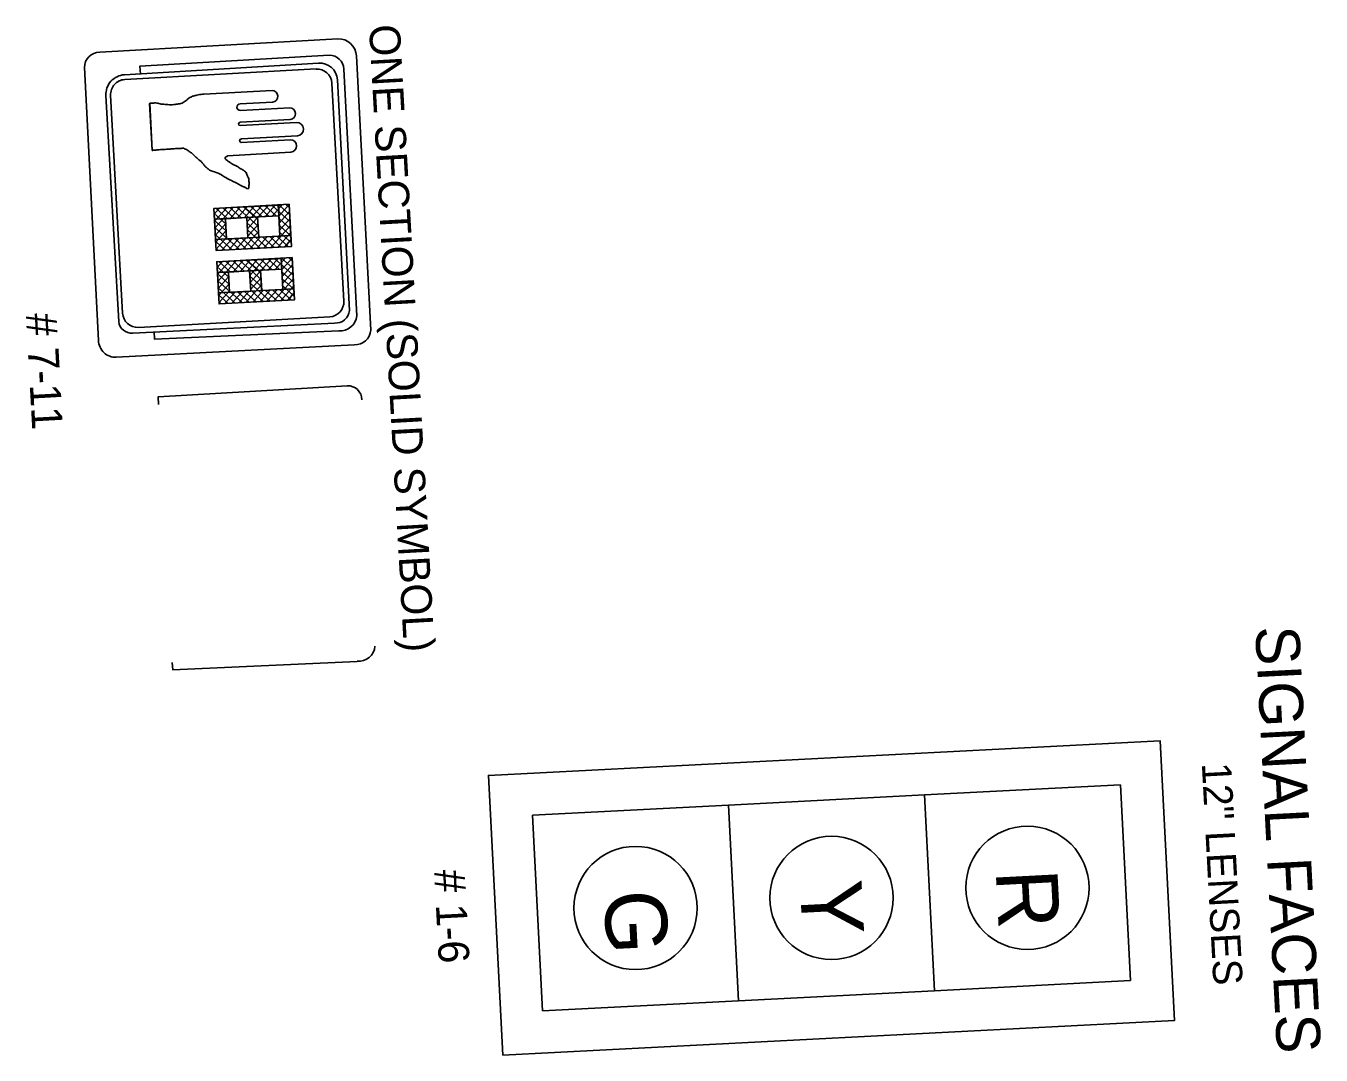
# Model space of a CAD drawing. Extents: x -218554 to 420030, y -566264 to -483460.
# Drawn here: x -218553.8 to -218475.3, y -483522.4 to -483459.9 of the extents above; entities that cross this region are included whole.
import ezdxf

# ---------------------------------------------------------------- set-up
doc = ezdxf.new("R2010")
doc.units = 0
for name, color, linetype in [('G-ANNO-STMP', 7, 'Continuous'), ('Level 1', 7, 'Continuous'), ('Level 61', 7, 'Continuous')]:
    doc.layers.add(name, color=color, linetype=linetype)

msp = doc.modelspace()

# ---------------------------------------------------------------- linework, layer by layer
at = {"layer": 'Level 1'}
for p, q in [((-218534.899, -483460.726), (-218549.338, -483461.533)), ((-218532.891, -483478.4), (-218533.762, -483461.757)), ((-218550.267, -483462.458), (-218549.412, -483479.034)), ((-218536.07, -483462.195), (-218547.834, -483462.901)), ((-218533.745, -483477.527), (-218534.536, -483462.56)), ((-218534.19, -483477.206), (-218534.915, -483463.203)), ((-218548.965, -483464.164), (-218548.185, -483477.873)), ((-218543.022, -483464.078), (-218538.886, -483463.85)), ((-218538.886, -483463.85), (-218543.022, -483464.078)), ((-218546.164, -483467.478), (-218546.32, -483464.647)), ((-218546.305, -483464.631), (-218546.165, -483467.49)), ((-218538.855, -483464.56), (-218540.827, -483464.668)), ((-218540.827, -483464.668), (-218538.855, -483464.56)), ((-218540.805, -483465.068), (-218537.813, -483464.903)), ((-218537.813, -483464.903), (-218540.805, -483465.068)), ((-218540.82, -483465.986), (-218537.395, -483465.797)), ((-218537.395, -483465.797), (-218540.82, -483465.986)), ((-218537.782, -483465.614), (-218540.816, -483465.781)), ((-218540.816, -483465.781), (-218537.782, -483465.614)), ((-218537.342, -483466.612), (-218540.743, -483466.799)), ((-218540.743, -483466.799), (-218537.342, -483466.612)), ((-218546.167, -483467.492), (-218546.164, -483467.478)), ((-218540.748, -483467.004), (-218537.763, -483466.84)), ((-218537.763, -483466.84), (-218540.748, -483467.004)), ((-218537.746, -483467.601), (-218541.588, -483467.812)), ((-218541.588, -483467.812), (-218537.746, -483467.601)), ((-218542.396, -483471.323), (-218541.693, -483471.952)), ((-218542.062, -483470.991), (-218542.393, -483471.361)), ((-218541.637, -483470.968), (-218542.37, -483471.786)), ((-218541.213, -483470.944), (-218542.347, -483472.21)), ((-218542.3, -483471.004), (-218541.598, -483471.633)), ((-218541.876, -483470.981), (-218541.174, -483471.61)), ((-218541.451, -483470.957), (-218540.749, -483471.586)), ((-218540.788, -483470.921), (-218541.417, -483471.623)), ((-218541.027, -483470.934), (-218539.727, -483472.098)), ((-218540.364, -483470.898), (-218540.993, -483471.6)), ((-218540.602, -483470.911), (-218539.75, -483471.674)), ((-218539.939, -483470.874), (-218540.568, -483471.576)), ((-218539.514, -483470.851), (-218540.408, -483471.848)), ((-218539.09, -483470.827), (-218540.385, -483472.273)), ((-218540.178, -483470.887), (-218539.475, -483471.516)), ((-218539.753, -483470.864), (-218539.051, -483471.493)), ((-218539.328, -483470.841), (-218538.626, -483471.47)), ((-218538.665, -483470.804), (-218539.294, -483471.506)), ((-218538.904, -483470.817), (-218537.783, -483471.821)), ((-218538.241, -483470.781), (-218538.87, -483471.483)), ((-218538.479, -483470.794), (-218537.807, -483471.396)), ((-218537.84, -483470.784), (-218538.469, -483471.487)), ((-218537.817, -483471.209), (-218538.446, -483471.911)), ((-218538.055, -483470.77), (-218537.83, -483470.972)), ((-218542.372, -483471.747), (-218541.67, -483472.376)), ((-218542.349, -483472.172), (-218540.872, -483473.495)), ((-218541.694, -483471.933), (-218542.323, -483472.635)), ((-218540.423, -483471.569), (-218540.356, -483472.798)), ((-218540.406, -483471.894), (-218539.703, -483472.523)), ((-218539.732, -483471.995), (-218540.361, -483472.698)), ((-218539.758, -483471.532), (-218539.69, -483472.762)), ((-218537.77, -483472.058), (-218538.963, -483473.389)), ((-218538.462, -483471.616), (-218537.76, -483472.245)), ((-218538.439, -483472.041), (-218537.737, -483472.67)), ((-218537.794, -483471.633), (-218538.423, -483472.336)), ((-218542.325, -483472.596), (-218541.296, -483473.518)), ((-218541.671, -483472.357), (-218542.3, -483473.059)), ((-218541.647, -483472.782), (-218542.276, -483473.484)), ((-218541.306, -483472.851), (-218541.935, -483473.553)), ((-218540.881, -483472.827), (-218541.51, -483473.53)), ((-218541.15, -483472.842), (-218540.447, -483473.471)), ((-218540.457, -483472.804), (-218541.086, -483473.506)), ((-218540.725, -483472.819), (-218540.023, -483473.448)), ((-218539.709, -483472.42), (-218540.661, -483473.483)), ((-218540.382, -483472.319), (-218539.174, -483473.401)), ((-218540.359, -483472.743), (-218539.598, -483473.424)), ((-218539.607, -483472.757), (-218540.236, -483473.46)), ((-218539.183, -483472.734), (-218539.812, -483473.436)), ((-218539.451, -483472.749), (-218538.749, -483473.378)), ((-218538.758, -483472.711), (-218539.387, -483473.413)), ((-218539.027, -483472.725), (-218538.324, -483473.354)), ((-218538.602, -483472.702), (-218537.9, -483473.331)), ((-218537.747, -483472.483), (-218538.538, -483473.366)), ((-218538.416, -483472.465), (-218537.713, -483473.094)), ((-218537.724, -483472.907), (-218538.114, -483473.343)), ((-218542.302, -483473.021), (-218541.721, -483473.541)), ((-218542.279, -483473.445), (-218542.145, -483473.565)), ((-218541.884, -483474.228), (-218542.215, -483474.599)), ((-218541.459, -483474.205), (-218542.192, -483475.023)), ((-218541.034, -483474.182), (-218542.168, -483475.448)), ((-218542.122, -483474.242), (-218541.42, -483474.871)), ((-218541.698, -483474.218), (-218540.995, -483474.847)), ((-218541.273, -483474.195), (-218540.571, -483474.824)), ((-218540.61, -483474.158), (-218541.239, -483474.861)), ((-218540.848, -483474.171), (-218539.548, -483475.336)), ((-218540.185, -483474.135), (-218540.814, -483474.837)), ((-218540.424, -483474.148), (-218539.572, -483474.911)), ((-218539.761, -483474.111), (-218540.39, -483474.814)), ((-218539.336, -483474.088), (-218540.23, -483475.086)), ((-218538.912, -483474.065), (-218540.206, -483475.51)), ((-218539.999, -483474.125), (-218539.297, -483474.754)), ((-218539.575, -483474.101), (-218538.872, -483474.73)), ((-218539.15, -483474.078), (-218538.448, -483474.707)), ((-218538.487, -483474.041), (-218539.116, -483474.744)), ((-218538.726, -483474.054), (-218537.605, -483475.058)), ((-218538.063, -483474.018), (-218538.692, -483474.72)), ((-218538.301, -483474.031), (-218537.628, -483474.633)), ((-218537.662, -483474.022), (-218538.291, -483474.724)), ((-218537.639, -483474.446), (-218538.268, -483475.148)), ((-218537.876, -483474.008), (-218537.652, -483474.209)), ((-218542.217, -483474.56), (-218541.515, -483475.189)), ((-218542.194, -483474.985), (-218541.492, -483475.614)), ((-218541.516, -483475.17), (-218542.145, -483475.872)), ((-218540.245, -483474.806), (-218540.177, -483476.036)), ((-218540.227, -483475.131), (-218539.525, -483475.76)), ((-218539.554, -483475.233), (-218540.183, -483475.935)), ((-218539.58, -483474.769), (-218539.512, -483475.999)), ((-218537.592, -483475.295), (-218538.784, -483476.627)), ((-218538.284, -483474.854), (-218537.582, -483475.483)), ((-218538.261, -483475.278), (-218537.558, -483475.907)), ((-218537.615, -483474.871), (-218538.244, -483475.573)), ((-218542.17, -483475.409), (-218540.693, -483476.732)), ((-218542.147, -483475.834), (-218541.118, -483476.755)), ((-218541.493, -483475.594), (-218542.122, -483476.297)), ((-218541.469, -483476.019), (-218542.098, -483476.721)), ((-218541.127, -483476.088), (-218541.756, -483476.79)), ((-218540.703, -483476.065), (-218541.332, -483476.767)), ((-218540.971, -483476.079), (-218540.269, -483476.708)), ((-218540.278, -483476.041), (-218540.907, -483476.744)), ((-218540.547, -483476.056), (-218539.844, -483476.685)), ((-218539.531, -483475.657), (-218540.483, -483476.72)), ((-218540.204, -483475.556), (-218538.995, -483476.638)), ((-218540.18, -483475.98), (-218539.42, -483476.662)), ((-218539.429, -483475.995), (-218540.058, -483476.697)), ((-218539.005, -483475.971), (-218539.634, -483476.673)), ((-218539.273, -483475.986), (-218538.571, -483476.615)), ((-218538.58, -483475.948), (-218539.209, -483476.65)), ((-218538.848, -483475.963), (-218538.146, -483476.592)), ((-218538.424, -483475.939), (-218537.722, -483476.568)), ((-218537.569, -483475.72), (-218538.36, -483476.603)), ((-218538.237, -483475.703), (-218537.535, -483476.332)), ((-218542.124, -483476.258), (-218541.543, -483476.779)), ((-218542.1, -483476.683), (-218541.967, -483476.802)), ((-218537.545, -483476.144), (-218537.935, -483476.58)), ((-218547.327, -483478.585), (-218535.092, -483477.969)), ((-218548.331, -483480.045), (-218533.902, -483479.285))]:
    msp.add_line(p, q, dxfattribs=at)
for points in [[(-218535.423, -483461.711), (-218546.895, -483462.377), (-218546.869, -483462.859)], [(-218536.215, -483462.551), (-218547.818, -483463.19)], [(-218534.529, -483476.634), (-218535.257, -483463.409)], [(-218548.676, -483464.148), (-218547.948, -483477.373)], [(-218540.356, -483472.798), (-218541.643, -483472.869), (-218541.71, -483471.639), (-218540.423, -483471.569)], [(-218539.69, -483472.762), (-218538.403, -483472.691), (-218538.471, -483471.461), (-218539.758, -483471.532)], [(-218540.177, -483476.036), (-218541.464, -483476.107), (-218541.532, -483474.877), (-218540.245, -483474.806)], [(-218539.512, -483475.999), (-218538.225, -483475.928), (-218538.293, -483474.698), (-218539.58, -483474.769)], [(-218546.99, -483478.23), (-218535.386, -483477.591)], [(-218546.04, -483478.511), (-218546.016, -483478.945), (-218534.836, -483478.439)], [(-218534.319, -483481.772), (-218545.79, -483482.438), (-218545.764, -483482.92)], [(-218544.936, -483498.572), (-218544.911, -483499.006), (-218533.731, -483498.5)]]:
    msp.add_lwpolyline(points, dxfattribs=at)
for points in [[(-218537.842, -483470.759), (-218537.701, -483473.32), (-218542.272, -483473.572), (-218542.413, -483471.01)], [(-218542.413, -483471.01), (-218542.378, -483471.666), (-218538.471, -483471.461), (-218538.505, -483470.806)], [(-218537.842, -483470.759), (-218537.742, -483472.656), (-218538.403, -483472.691), (-218538.502, -483470.793)], [(-218541.71, -483471.639), (-218541.646, -483472.861), (-218542.307, -483472.895), (-218542.371, -483471.674)], [(-218539.758, -483471.532), (-218539.693, -483472.764), (-218540.356, -483472.798), (-218540.42, -483471.567)], [(-218537.742, -483472.656), (-218537.707, -483473.333), (-218542.272, -483473.572), (-218542.307, -483472.895)], [(-218537.664, -483473.996), (-218537.523, -483476.557), (-218542.093, -483476.809), (-218542.234, -483474.248)], [(-218542.234, -483474.248), (-218542.2, -483474.903), (-218538.293, -483474.698), (-218538.327, -483474.043)], [(-218537.664, -483473.996), (-218537.564, -483475.894), (-218538.225, -483475.928), (-218538.324, -483474.031)], [(-218541.532, -483474.877), (-218541.468, -483476.098), (-218542.129, -483476.133), (-218542.193, -483474.911)], [(-218539.58, -483474.769), (-218539.515, -483476.001), (-218540.177, -483476.036), (-218540.242, -483474.804)], [(-218537.564, -483475.894), (-218537.529, -483476.57), (-218542.093, -483476.809), (-218542.129, -483476.133)]]:
    msp.add_lwpolyline(points, close=True, dxfattribs=at)
for centre, radius, start, end in [((-218534.847, -483461.81), 1.086, 2.77432, 92.77432), ((-218549.339, -483462.46), 0.927, 89.93321, 179.93321), ((-218535.404, -483462.579), 0.869, 1.27514, 91.27514), ((-218536.165, -483463.459), 0.909, 3.15216, 93.15216), ((-218535.996, -483463.276), 1.083, 3.88192, 93.88192), ((-218547.768, -483464.098), 1.198, 93.15216, 183.15216), ((-218547.768, -483464.098), 0.909, 93.15216, 183.15216), ((-218538.891, -483464.205), 0.356, 275.81971, 89.16653), ((-218538.891, -483464.205), 0.356, 275.81971, 89.16653), ((-218540.817, -483464.868), 0.2, 93.15216, 273.15216), ((-218540.817, -483464.868), 0.2, 93.15216, 273.15216), ((-218537.818, -483465.259), 0.356, 275.81971, 89.16653), ((-218537.818, -483465.259), 0.356, 275.81971, 89.16653), ((-218540.818, -483465.883), 0.102, 88.57477, 268.57477), ((-218540.818, -483465.883), 0.102, 88.57477, 268.57477), ((-218537.392, -483466.206), 0.409, 277.05213, 90.39894), ((-218537.392, -483466.206), 0.409, 277.05213, 90.39894), ((-218540.745, -483466.9), 0.104, 88.04746, 268.04746), ((-218540.745, -483466.9), 0.104, 88.04746, 268.04746), ((-218537.777, -483467.221), 0.381, 274.62974, 87.97656), ((-218537.777, -483467.221), 0.381, 274.62974, 87.97656), ((-218535.437, -483476.684), 0.909, 273.15216, 3.15216), ((-218547.04, -483477.323), 0.909, 183.15216, 273.15216), ((-218535.023, -483477.136), 0.836, 265.22621, 355.22621), ((-218534.747, -483477.437), 1.005, 264.91062, 354.91062), ((-218547.4, -483477.8), 0.788, 185.26181, 275.26181), ((-218533.839, -483478.337), 0.95, 266.18024, 356.18024), ((-218548.365, -483478.999), 1.047, 181.91264, 271.91264), ((-218534.3, -483482.64), 0.869, 1.27514, 91.27514), ((-218533.642, -483497.498), 1.005, 264.91062, 354.91062)]:
    msp.add_arc(centre, radius, start, end, dxfattribs=at)
for points in [[(-218546.305, -483464.631), (-218546.148, -483464.622), (-218545.882, -483464.618), (-218545.603, -483464.681), (-218545.287, -483464.703), (-218545.109, -483464.723), (-218544.765, -483464.704), (-218544.482, -483464.659), (-218544.337, -483464.621), (-218544.099, -483464.46), (-218543.862, -483464.29), (-218543.661, -483464.19), (-218543.447, -483464.139), (-218543.282, -483464.101), (-218543.175, -483464.095), (-218543.022, -483464.078)], [(-218543.022, -483464.078), (-218543.175, -483464.095), (-218543.282, -483464.101), (-218543.447, -483464.139), (-218543.661, -483464.19), (-218543.862, -483464.29), (-218544.099, -483464.46), (-218544.337, -483464.621), (-218544.482, -483464.659), (-218544.765, -483464.704), (-218545.109, -483464.723), (-218545.287, -483464.703), (-218545.603, -483464.681), (-218545.882, -483464.618), (-218546.148, -483464.622), (-218546.305, -483464.631)], [(-218541.587, -483467.81), (-218541.591, -483467.838), (-218541.668, -483467.882), (-218541.725, -483467.934), (-218541.732, -483467.964), (-218541.721, -483468.013), (-218541.679, -483468.04), (-218541.576, -483468.123), (-218541.494, -483468.187), (-218541.433, -483468.223), (-218541.382, -483468.26), (-218541.29, -483468.324), (-218541.209, -483468.358), (-218541.098, -483468.412), (-218541.037, -483468.447), (-218540.925, -483468.51), (-218540.822, -483468.583), (-218540.721, -483468.637), (-218540.619, -483468.7), (-218540.547, -483468.755), (-218540.464, -483468.839), (-218540.418, -483468.945), (-218540.385, -483469.002), (-218540.352, -483469.089), (-218540.318, -483469.165), (-218540.291, -483469.283), (-218540.286, -483469.381), (-218540.279, -483469.508), (-218540.283, -483469.626), (-218540.294, -483469.764), (-218540.312, -483469.805), (-218540.34, -483469.816), (-218540.471, -483469.764), (-218540.542, -483469.729), (-218540.614, -483469.694), (-218540.694, -483469.659), (-218540.744, -483469.642), (-218540.876, -483469.57), (-218541.06, -483469.462), (-218541.353, -483469.32), (-218541.687, -483469.142), (-218541.922, -483468.998), (-218542.074, -483468.917), (-218542.215, -483468.846), (-218542.328, -483468.808), (-218542.385, -483468.787), (-218542.627, -483468.713), (-218542.801, -483468.584), (-218542.925, -483468.483), (-218543.051, -483468.332), (-218543.126, -483468.238), (-218543.395, -483467.997), (-218543.622, -483467.783), (-218543.778, -483467.644), (-218543.951, -483467.526), (-218544.028, -483467.467), (-218544.136, -483467.418), (-218544.236, -483467.365), (-218544.453, -483467.377), (-218544.647, -483467.377), (-218544.824, -483467.387), (-218545.059, -483467.41), (-218545.285, -483467.423), (-218545.648, -483467.443), (-218545.941, -483467.468), (-218546.048, -483467.483), (-218546.127, -483467.488), (-218546.165, -483467.49)], [(-218546.165, -483467.49), (-218546.127, -483467.488), (-218546.048, -483467.483), (-218545.941, -483467.468), (-218545.648, -483467.443), (-218545.285, -483467.423), (-218545.059, -483467.41), (-218544.824, -483467.387), (-218544.647, -483467.377), (-218544.453, -483467.377), (-218544.236, -483467.365), (-218544.136, -483467.418), (-218544.028, -483467.467), (-218543.951, -483467.526), (-218543.778, -483467.644), (-218543.622, -483467.783), (-218543.395, -483467.997), (-218543.126, -483468.238), (-218543.051, -483468.332), (-218542.925, -483468.483), (-218542.801, -483468.584), (-218542.627, -483468.713), (-218542.385, -483468.787), (-218542.328, -483468.808), (-218542.215, -483468.846), (-218542.074, -483468.917), (-218541.922, -483468.998), (-218541.687, -483469.142), (-218541.353, -483469.32), (-218541.06, -483469.462), (-218540.876, -483469.57), (-218540.744, -483469.642), (-218540.694, -483469.659), (-218540.614, -483469.694), (-218540.542, -483469.729), (-218540.471, -483469.764), (-218540.34, -483469.816), (-218540.312, -483469.805), (-218540.294, -483469.764), (-218540.283, -483469.626), (-218540.279, -483469.508), (-218540.286, -483469.381), (-218540.291, -483469.283), (-218540.318, -483469.165), (-218540.352, -483469.089), (-218540.385, -483469.002), (-218540.418, -483468.945), (-218540.464, -483468.839), (-218540.547, -483468.755), (-218540.619, -483468.7), (-218540.721, -483468.637), (-218540.822, -483468.583), (-218540.925, -483468.51), (-218541.037, -483468.447), (-218541.098, -483468.412), (-218541.209, -483468.358), (-218541.29, -483468.324), (-218541.382, -483468.26), (-218541.433, -483468.223), (-218541.494, -483468.187), (-218541.576, -483468.123), (-218541.679, -483468.04), (-218541.721, -483468.013), (-218541.732, -483467.964), (-218541.725, -483467.934), (-218541.668, -483467.882), (-218541.591, -483467.838), (-218541.587, -483467.81)]]:
    msp.add_spline(points, degree=3, dxfattribs=at)
at = {"layer": 'Level 61'}
for p, q in [((-218499.314, -483506.609), (-218511.199, -483507.222)), ((-218487.429, -483505.996), (-218499.314, -483506.609)), ((-218499.314, -483506.609), (-218498.701, -483518.494)), ((-218487.429, -483505.996), (-218486.816, -483517.88)), ((-218511.199, -483507.222), (-218523.084, -483507.835)), ((-218511.199, -483507.222), (-218510.586, -483519.107)), ((-218523.084, -483507.835), (-218522.471, -483519.72)), ((-218498.701, -483518.494), (-218510.586, -483519.107)), ((-218486.816, -483517.88), (-218498.701, -483518.494)), ((-218510.586, -483519.107), (-218522.471, -483519.72))]:
    msp.add_line(p, q, dxfattribs=at)
msp.add_lwpolyline([(-218524.886, -483522.398), (-218484.138, -483520.296), (-218485.014, -483503.317), (-218525.762, -483505.42)], close=True, dxfattribs=at)
for centre in [(-218493.065, -483512.245), (-218516.835, -483513.471), (-218504.95, -483512.858)]:
    msp.add_circle(centre, 3.74, dxfattribs=at)

# ---------------------------------------------------------------- texts
at = {"layer": 'G-ANNO-STMP'}
for s, height, rotation, p in [('ONE SECTION (SOLID SYMBOL)', 1.86667, 273.19877, (-218533.006, -483459.894)), ('# 7-11', 1.8667, 273.19877, (-218553.823, -483477.414)), ('# 1-6', 1.8667, 272.95326, (-218529.057, -483511.186))]:
    msp.add_text(s, height=height, rotation=rotation, dxfattribs=at).set_placement(p)
at = {"layer": 'Level 61'}
for s, height, rotation, p in [('SIGNAL FACES', 2.66667, 272.95326, (-218479.253, -483496.418)), ('12" LENSES', 1.7778, 273.02529, (-218482.488, -483504.688)), ('R', 3.739, 272.95326, (-218494.991, -483511.211)), ('Y', 3.739, 272.95326, (-218506.873, -483511.868)), ('G', 3.739, 272.95326, (-218518.759, -483512.47))]:
    msp.add_text(s, height=height, rotation=rotation, dxfattribs=at).set_placement(p)

doc.saveas('drawing.dxf')
